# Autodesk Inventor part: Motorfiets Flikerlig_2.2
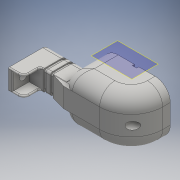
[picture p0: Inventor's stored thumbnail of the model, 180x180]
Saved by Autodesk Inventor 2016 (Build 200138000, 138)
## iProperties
Created: 2016-11
Part Number: Motorfiets Flikerlig_2.2
Material: Generic
Document SubType Name: Modeling
Designer: user
Density: 1 g/cm^3
Appearance: Default
Author: user
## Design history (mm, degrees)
sketch "Sketch1"
  geometry: L1 (0, 0)-(-62, 0); L2 (-62, 0)-(-62, -46); L3 (-62, -46)-(0, -46); L4 (0, -46)-(0, 0)
  constraints: 8 end point, 2 parallel, 1 horizontal, 1 perpendicular
  dimensions: "d0" = 62 distance of L3.end L2.end; "d1" = 46 distance of L2.end L1.end
extrude "Extrusion1" new body sketch "Sketch1" distance "d2" = 36; taper "d3" = 0 deg
sketch "Sketch2"
  geometry: L1 (13.5, 25.5)-(32.5, 25.5); L2 (32.5, 25.5)-(32.5, 4); L3 (32.5, 4)-(13.5, 4); L4 (13.5, 4)-(13.5, 25.5); L5 (0, 36)-(46, 36) reference; L6 (0, 0)-(46, 0) reference; L7 (0, 0)-(0, 36) reference; L8 (46, 0)-(46, 36) reference
  constraints: 8 end point, 2 parallel, 1 horizontal, 1 perpendicular
  dimensions: "d4" = 21.5 distance between parallel lines of L3 L1; "d8" = 10.5 distance between parallel lines of L5 L1; "d9" = 4 distance between parallel lines of L6 L3 (derived); "d10" = 46 distance between parallel lines of L7 L8 (derived); "d11" = 19 distance between parallel lines of L4 L2; "d12" = 13.5 distance between parallel lines of L7 L4; "d13" = 13.5 distance between parallel lines of L8 L2 (derived)
extrude "Extrusion2" join sketch "Sketch2" distance "d14" = 40; taper "d15" = 0 deg
sketch "Sketch3"
  geometry: L1 (0, 0)-(-40, 0) reference; L2 (0, 19)-(-40, 19) reference; L3 (-40, 0)-(-26, 0); L4 (-26, 0)-(-26, 19); L5 (-26, 19)-(-40, 19); L6 (-40, 19)-(-40, 0); 1 further point
  constraints: 8 end point, 2 parallel, 1 horizontal, 1 perpendicular, 1 point on line
  dimensions: "d16" = 14 distance between parallel lines of L6 L4
extrude "Extrusion3" join sketch "Sketch3" distance "d17" = 15; taper "d18" = 0 deg
sketch "Sketch4"
  geometry: L1 (1.5, 44.5)-(60.5, 44.5); L2 (60.5, 44.5)-(60.5, 1.5); L3 (60.5, 1.5)-(1.5, 1.5); L4 (1.5, 1.5)-(1.5, 44.5); L5 (62, 46)-(0, 46) reference; L6 (62, 0)-(62, 46) reference; L7 (0, 0)-(62, 0) reference; L8 (0, 46)-(0, 0) reference; L9 (2.5, 43.5)-(59.5, 43.5); L10 (59.5, 43.5)-(59.5, 2.5); L11 (59.5, 2.5)-(2.5, 2.5); L12 (2.5, 2.5)-(2.5, 43.5); C1 r 3 at (54, 23); C2 r 4.5 at (54, 23)
  constraints: 16 end point, 4 parallel, 2 centre point, 2 horizontal, 2 perpendicular, 1 coincident
  dimensions: "d19" = 1.5 distance between parallel lines of L5 L1; "d20" = 1.5 distance between parallel lines of L6 L2; "d21" = 1.5 distance between parallel lines of L7 L3; "d22" = 1.5 distance between parallel lines of L8 L4; "d23" = 6 diameter of C1; "d24" = 9 diameter of C2; "d25" = 8 distance from line of L6 C1.centre; "d26" = 1 distance between parallel lines of L1 L9; "d27" = 1 distance between parallel lines of L2 L10; "d28" = 1 distance between parallel lines of L3 L11; "d29" = 1 distance between parallel lines of L4 L12
extrude "Extrusion4" cut sketch "Sketch4" distance "d30" = 4; taper "d31" = 0 deg
extrude "Extrusion5" cut sketch "Sketch4" distance "d32" = 32; taper "d33" = 0 deg
extrude "Extrusion6" cut sketch "Sketch4" distance "d34" = 12; taper "d35" = 0 deg
fillet "Fillet1" dims "d36" = 26
fillet "Fillet2" dims "d37" = 29
fillet "Fillet3" dims "d38" = 12
fillet "Fillet4" dims "d39" = 12
fillet "Fillet5" dims "d40" = 12
fillet "Fillet6" dims "d41" = 12
fillet "Fillet7" dims "d42" = 12
fillet "Fillet8" dims "d43" = 12
fillet "Fillet9" dims "d44" = 14
sketch "Sketch5"
  geometry: L1 (-13, 5.5)-(-5, 5.5); L2 (-5, 5.5)-(-5, 3.5); L3 (-5, 3.5)-(-13, 3.5); L4 (-13, 3.5)-(-13, 5.5); L5 (0.5, 10.5)-(-18.5, 10.5) reference; L6 (0.5, 10.5)-(0, 0) reference; L7 (-18, 0)-(-18.5, 10.5) reference; L8 (14, -11.5)-(14, 10.5) reference; L9 (-32, 10.5)-(-32, -11.5) reference; 1 further point
  constraints: 8 end point, 2 parallel, 1 horizontal, 1 perpendicular
  dimensions: "d45" = 5 distance between parallel lines of L5 L1; "d46" = 2 distance between parallel lines of L1 L3; "d47" = 8 distance between parallel lines of L2 L4; "d48" = 18 distance between parallel lines of L6 L7 (derived); "d49" = 5 distance between parallel lines of L7 L4; "d50" = 5 distance between parallel lines of L6 L2 (derived)
extrude "Extrusion7" cut sketch "Sketch5" distance "d53" = 3; taper "d54" = 0 deg
sketch "Sketch6"
  geometry: L1 (0, 27)-(2.5, 27) reference; L2 (1.5, 13.5)-(1.5, 32.5) reference; L3 (2.5, 27)-(1.5, 27); L4 (1.5, 27)-(1.5, 19); L5 (1.5, 19)-(2.5, 19); L6 (2.5, 19)-(2.5, 27); 1 further point
  constraints: 8 end point, 2 parallel, 1 horizontal, 1 perpendicular, 1 point on line
  dimensions: "d164" = 8 distance between parallel lines of L1 L5
extrude "Extrusion8" cut sketch "Sketch6" distance "d55" = 1; taper "d56" = 0 deg
sketch "Sketch7"
  geometry: L1 (34, 0)-(0, 0) reference; L2 (15, 0)-(19, 0); L3 (19, 0)-(19, -2); L4 (19, -2)-(15, -2); L5 (15, -2)-(15, 0); L6 (48, -10.5)-(48, 0) reference; L7 (-14, 0)-(-14, -7) reference; 1 further point
  constraints: 8 end point, 2 parallel, 1 horizontal, 1 perpendicular, 1 point on line
  dimensions: "d57" = 4 distance of L3.end L4.end; "d58" = 2 distance of L2.end L3.end; "d59" = 29 distance between parallel lines of L6 L3; "d60" = 29 distance between parallel lines of L7 L5 (derived); "d61" = 62 distance between parallel lines of L6 L7 (derived)
extrude "Extrusion9" cut sketch "Sketch7" distance "d62" = 2; taper "d63" = 0 deg
sketch "Sketch8"
  geometry: 2 further points
hole "Hole1" sketch "Sketch8" at (0, 0) diameter "d64" = 3.5; stored, may be unused: countersink angle "d68" = 90 deg, drill point angle "d70" = 118 deg; dims "d65" = 6, "d66" = 4, "d67" = 2, "d69" = 8
workplane "Work Plane1"
sketch "Sketch9"
  geometry: C1 r 1.75 at (54, 23) reference; 2 further points
  constraints: 1 coincident
hole "Hole2" sketch "Sketch9" at (54, 23) diameter "d72" = 7; stored, may be unused: countersink angle "d76" = 90 deg, drill point angle "d78" = 118 deg; dims "d73" = 6, "d74" = 4, "d75" = 2, "d77" = 8
fillet "Fillet15" dims "d88" = 2
fillet "Fillet16" dims "d89" = 2
sketch "Sketch10"
  geometry: L1 (-24.197, 36.5)-(14, 36.5) reference; L2 (-3.2, 36.5)-(-5.6, 36.5); L3 (-5.6, 36.5)-(-5.6, 15); L4 (-5.6, 15)-(-3.2, 15); L5 (-3.2, 15)-(-3.2, 36.5); L6 (-9.6, 36.5)-(-12, 36.5); L7 (-12, 36.5)-(-12, 15); L8 (-12, 15)-(-9.6, 15); L9 (-9.6, 15)-(-9.6, 36.5); L10 (-26, 36.5)-(-26, 47) reference; 3 further points
  constraints: 16 end point, 4 parallel, 2 horizontal, 2 perpendicular, 2 point on line
  dimensions: "d91" = 2.4 distance between parallel lines of L9 L7; "d92" = 2.4 distance between parallel lines of L5 L3; "d93" = 14 distance between parallel lines of L10 L7; "d94" = 4 distance between parallel lines of L9 L3
sketch "Sketch11"
  geometry: L1 (26, 19)-(23.6, 19); L2 (23.6, 19)-(23.6, 0); L3 (23.6, 0)-(26, 0); L4 (26, 0)-(26, 19); L5 (40, 18.5)-(40, 0.5) reference; L6 (19.6, 19)-(17.2, 19); L7 (17.2, 19)-(17.2, 0); L8 (17.2, 0)-(19.6, 0); L9 (19.6, 0)-(19.6, 19); 1 further point
  constraints: 16 end point, 4 parallel, 2 horizontal, 2 perpendicular
  dimensions: "d95" = 2.4 distance between parallel lines of L2 L4; "d98" = 14 distance between parallel lines of L5 L4; "d99" = 4 distance between parallel lines of L2 L9; "d100" = 2.4 distance between parallel lines of L9 L7
sketch "Sketch12"
  geometry: L1 (38.197, 36.5)-(0, 36.5) reference; L2 (26, 36.5)-(23.6, 36.5); L3 (23.6, 36.5)-(23.6, 15); L4 (23.6, 15)-(26, 15); L5 (26, 15)-(26, 36.5); L6 (40, 47)-(40, 11) reference; L7 (19.6, 36.5)-(17.2, 36.5); L8 (17.2, 36.5)-(17.2, 15); L9 (17.2, 15)-(19.6, 15); L10 (19.6, 15)-(19.6, 36.5); 5 further points; 1 other entity
  constraints: 16 end point, 4 parallel, 2 horizontal, 2 perpendicular, 2 point on line, 1 other
  dimensions: "d102" = 2.4 distance between parallel lines of L5 L3; "d103" = 14 distance between parallel lines of L6 L5; "d104" = 2.4 distance between parallel lines of L8 L10; "d105" = 4 distance between parallel lines of L3 L10
workplane "Work Plane2"
sketch "Sketch13"
  geometry: L1 (38.197, 19)-(0, 19) reference; L2 (38.197, 0)-(0, 0) reference; L3 (26, 19)-(23.6, 19); L4 (23.6, 19)-(23.6, 0); L5 (23.6, 0)-(26, 0); L6 (26, 0)-(26, 19); L7 (19.6, 19)-(17.2, 19); L8 (17.2, 19)-(17.2, 0); L9 (17.2, 0)-(19.6, 0); L10 (19.6, 0)-(19.6, 19); 2 further points
  constraints: 16 end point, 4 parallel, 4 point on line, 2 horizontal, 2 perpendicular
  dimensions: "d107" = 2.4 distance between parallel lines of L6 L4; "d108" = 2.4 distance between parallel lines of L8 L10; "d109" = 4 distance between parallel lines of L4 L10
extrude "Extrusion10" cut sketch "Sketch12" distance "d111" = 1; taper "d112" = 0 deg
extrude "Extrusion11" cut sketch "Sketch11" distance "d113" = 1; taper "d114" = 0 deg
extrude "Extrusion12" cut sketch "Sketch10" distance "d115" = 1; taper "d116" = 0 deg
extrude "Extrusion13" cut sketch "Sketch13" distance "d117" = 1; taper "d118" = 0 deg
loft "Loft2" dims "d120" = 0, "d121" = 90 deg, "d122" = 0, "d123" = 90 deg
  node "Edges3"
  node "Edges4"
fillet "Fillet22" dims "d127" = 5
fillet "Fillet23" dims "d128" = 5
fillet "Fillet24" dims "d129" = 2
fillet "Fillet27" dims "d132" = 5
sketch "Sketch14"
  geometry: L1 (19, -15)-(0, -15) reference; L2 (0, 0)-(19, 0) reference; L3 (19, -15)-(17, -15); L4 (17, -15)-(17, 0); L5 (17, 0)-(19, 0); L6 (19, 0)-(19, -15); L7 (0, -15)-(2, -15); L8 (2, -15)-(2, 0); L9 (2, 0)-(0, 0); L10 (0, 0)-(0, -15); L11 (17, -15)-(2, -15); L12 (2, -15)-(2, 0); L13 (2, 0)-(17, 0); L14 (17, 0)-(17, -15); 1 further point
  constraints: 24 end point, 6 parallel, 3 horizontal, 3 perpendicular, 2 point on line
  dimensions: "d133" = 2 distance of L4.end L5.end; "d134" = 2 distance of L9.end L8.end
extrude "Extrusion14" cut sketch "Sketch14" distance "d135" = 10; taper "d136" = 0 deg
fillet "Fillet28" dims "d137" = 5
fillet "Fillet29" dims "d138" = 2
fillet "Fillet30" dims "d139" = 1
fillet "Fillet31" dims "d140" = 1
sketch "Sketch15"
  geometry: L1 (27.5, 25.5)-(18.5, 25.5) reference; L2 (32.5, 20.5)-(32.5, -10) reference; L3 (13.5, 20.5)-(13.5, -10) reference; 2 further points
  dimensions: "d142" = 8 distance from line of L1 point (23, 17.5); "d143" = 9.5 distance from line of L2 point (23, 17.5); "d144" = 9.5 distance from line of L3 point (23, 17.5) (derived)
hole "Hole3" sketch "Sketch15" at (23, 17.5) diameter "d145" = 6; stored, may be unused: countersink angle "d149" = 90 deg, drill point angle "d151" = 118 deg; dims "d146" = 6, "d147" = 4, "d148" = 2, "d150" = 44
sketch "Sketch16"
  geometry: L1 (31.5, -11)-(14.5, -11) reference; L2 (32.5, 20.5)-(32.5, -10) reference; L3 (13.5, 20.5)-(13.5, -10) reference; 2 further points
  dimensions: "d152" = 9.5 distance from line of L1 point (23, -1.5); "d153" = 9.5 distance from line of L2 point (23, -1.5); "d154" = 9.5 distance from line of L3 point (23, -1.5) (derived)
hole "Hole4" sketch "Sketch16" at (23, -1.5) diameter "d155" = 7; stored, may be unused: countersink angle "d159" = 90 deg, drill point angle "d161" = 118 deg; dims "d156" = 6, "d157" = 4, "d158" = 2, "d160" = 4
fillet "Fillet32" dims "d162" = 8
fillet "Fillet33" dims "d163" = 8
workplane "Work Plane3"
mirror "Mirror1"
body "Solid1"
other parameters: "d71" = -3, "d106" = -21.5
